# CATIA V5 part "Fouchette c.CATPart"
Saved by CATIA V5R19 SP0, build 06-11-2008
Part number: Fouchette c
Bounding box of the stored display mesh (mm): x -10 to 30, y -62.897 to 62.897, z -40 to 71.812
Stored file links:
  F:\CFAO\Hberriche\Fouchette c.CATPart
  F:\CFAO\Hberriche\Fouchette b.CATPart
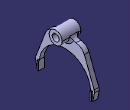
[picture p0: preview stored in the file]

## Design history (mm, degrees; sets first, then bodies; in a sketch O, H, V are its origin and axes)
Body1 (main body)
  Sketch1 on yz-plane, origin (0, 0, 0), H (0, 1, 0), V (0, 0, 1)
    line L1 (-54.7472, -20) -> (-54.7472, -40)
    point P1 (-54.7472, -20)
    point P2 (-54.7472, -40)
    point P3 (55.0096, -26.2979)
    arc A1 centre (0, -27) radius 55.1929 from (0, 28.1929) to (-54.7472, -20) ccw
    point P4 (0, -27)
    point P5 (-54.7472, -20)
    line L2 (-54.7472, -40) -> (-59.7472, -40)
    point P6 (-59.7472, -40)
    line L3 (-59.7472, -40) -> (-63.2737, -20)
    point P7 (-63.2737, -20)
    line L4 (-63.2737, -20) -> (-36.3479, 50)
    point P8 (-36.3479, 50)
    line L5 (-36.3479, 50) -> (0, 50)
    point P9 (-36.3479, 50)
    axis line L6 (0, 72.9256) -> (0, -136.9568)
    point P10 (0, 72.9256)
    point P12 (0, 50)
    point P13 (0, 28.1929)
    point P14 (0, 0)
    construction line L7 through (0, 0) direction (0, 1)
    point P17 (54.7472, -20)
    point P18 (54.7472, -40)
    point P20 (54.7472, -20)
    point P21 (59.7472, -40)
    point P22 (63.2737, -20)
    point P23 (36.3479, 50)
    point P24 (36.3479, 50)
    point P25 (0, 50)
    point P26 (0, 28.1929)
    line L8 (54.7472, -20) -> (54.7472, -40)
    arc A2 centre (0, -27) radius 55.1929 from (0, 28.1929) to (54.7472, -20) cw
    line L9 (54.7472, -40) -> (59.7472, -40)
    line L10 (59.7472, -40) -> (63.2737, -20)
    line L11 (63.2737, -20) -> (36.3479, 50)
    line L12 (36.3479, 50) -> (0, 50)
    distance P4 O = 27
    length L1 = 20
    radius A1 = 55.1929
    angle L3 L2 = 100
    length L2 = 5
    distance H L2 = 40
    distance L5 H = 50
    distance P7 H = 20
    length L4 = 75
    vertical: L1 V, L6 V
    coincidence: P4 V, P5 P1, P9 P8, P10 V, L6 P12, L6 P13, P12 P25, P13 P26, P17 P20, P23 P24
    horizontal: L2 H, L5 H
    symmetry: O P14 L6, V L7 L6, P1 P17 L6, P2 P18 L6, P5 P20 L6, P6 P21 L6, P7 P22 L6, P8 P23 L6, P9 P24 L6, P12 P25 L6, P13 P26 L6, L1 L8 L6, A1 A2 L6, L2 L9 L6, L3 L10 L6, L4 L11 L6, L5 L12 L6
  Pad1: profile Sketch1, direction (1, 0, 0), length 10
  Fillet1: radius 20, on edge [face of Pad1 from Sketch1.L4 | face of Pad1 from Sketch1.L5]; edge [face of Pad1 from Sketch1.L12 | face of Pad1 from Sketch1.L11]
  Fillet2: radius 10, on edge [face of Pad1 from Sketch1.L11 | face of Pad1 from Sketch1.L10]; edge [face of Pad1 from Sketch1.L3 | face of Pad1 from Sketch1.L4]
  Sketch2 on end face of Pad1, origin (10, 0, 0), H (0, 1, 0), V (0, 0, 1)
    circle A1 centre (0, 57.8119) radius 14
    point P1 (0, 57.8119)
    circle A2 centre (0, 57.8119) radius 7.5
    radius A2 = 7.5
    radius A1 = 14
    distance P1 H = 57.8119
    coincidence: P1 V
  Pad2: profile Sketch2, direction (1, 0, 0), length 20, mirrored extent
  Fillet3: radius 10, on edge [face of Pad2 from Sketch2.A1 | face of Pad1 from Sketch1.L12]
  Fillet4: radius 10, on edge [face of Pad1 from Sketch1.L5 | face of Pad2 from Sketch2.A1]
  Fillet5: radius 5, on edge [face of Pad2 from Sketch2.A1 | start face of Pad1]
  Fillet6: radius 5, on edge [end face of Pad1 | face of Pad2 from Sketch2.A1]
  Sketch3 on start face of Pad1, origin (0, 0, 0), H (0, -1, 0), V (0, 0, 1)
    axis line L1 (0, 18.2812) -> (0, -60.1212)
    point P1 (0, 18.2812)
    point P3 (-57.7472, -22)
    line L2 (-57.7472, -22) -> (-54.7472, -22)
    line L3 (-54.7472, -22) -> (-54.7472, -40)
    line L4 (-54.7472, -40) -> (-57.7472, -40)
    line L5 (-57.7472, -40) -> (-57.7472, -22)
    point P4 (-54.7472, -22)
    point P5 (-54.7472, -40)
    point P6 (-57.7472, -40)
    reference projected line E1 (-54.7472, -20) -> (-54.7472, -40) from edge [start face of Pad1 | face of Pad1 from Sketch1.L8]
    reference projected line E2 (-54.7472, -40) -> (-59.7472, -40) from edge [start face of Pad1 | face of Pad1 from Sketch1.L9]
    point P7 (57.7472, -22)
    point P8 (54.7472, -22)
    point P9 (54.7472, -40)
    point P10 (57.7472, -40)
    line L6 (57.7472, -22) -> (54.7472, -22)
    line L7 (54.7472, -22) -> (54.7472, -40)
    line L8 (54.7472, -40) -> (57.7472, -40)
    line L9 (57.7472, -40) -> (57.7472, -22)
    length L5 = 18
    length L2 = 3
    coincidence: P1 V, E1 L3, E2 L4
    vertical: L1 V, L3 V, L5 V
    horizontal: L2 H, L4 H
    symmetry: P3 P7 L1, P4 P8 L1, P5 P9 L1, P6 P10 L1, L2 L6 L1, L3 L7 L1, L4 L8 L1, L5 L9 L1
  Pad3: profile Sketch3, direction (-1, 0, 0), length 1.5
  Chamfer1: length 1, angle 45, on edge [start face of Pad1 | face of Pad3 from Sketch3.L5]; edge [start face of Pad1 | face of Pad3 from Sketch3.L9]
  Chamfer2: length 1, angle 45, on edge [face of Pad3 from Sketch3.L6 | start face of Pad1]; edge [face of Pad3 from Sketch3.L2 | start face of Pad1]
  Sketch4 on end face of Pad1, origin (10, 0, 0), H (0, 1, 0), V (0, 0, 1)
    point P1 (-57.7472, -22)
    line L1 (-57.7472, -22) -> (-54.7472, -22)
    line L2 (-54.7472, -22) -> (-54.7472, -40)
    line L3 (-54.7472, -40) -> (-57.7472, -40)
    line L4 (-57.7472, -40) -> (-57.7472, -22)
    point P2 (-54.7472, -22)
    point P3 (-54.7472, -40)
    point P4 (-57.7472, -40)
    reference projected line E1 (-54.7472, -40) -> (-54.7472, -20) from edge [face of Pad3 | end face of Pad1]
    reference projected line E2 (-59.7472, -40) -> (-54.7472, -40) from edge [face of Pad3 | end face of Pad1]
    axis line L5 (0, 14.1805) -> (0, -71.2709)
    point P5 (0, 14.1805)
    point P7 (57.7472, -22)
    point P8 (54.7472, -22)
    point P9 (54.7472, -40)
    point P10 (57.7472, -40)
    line L6 (57.7472, -22) -> (54.7472, -22)
    line L7 (54.7472, -22) -> (54.7472, -40)
    line L8 (54.7472, -40) -> (57.7472, -40)
    line L9 (57.7472, -40) -> (57.7472, -22)
    length L1 = 3
    length L4 = 18
    horizontal: L1 H, L3 H
    vertical: L2 V, L4 V, L5 V
    coincidence: E1 L2, E2 L3, P5 V
    symmetry: P1 P7 L5, P2 P8 L5, P3 P9 L5, P4 P10 L5, L1 L6 L5, L2 L7 L5, L3 L8 L5, L4 L9 L5
  Pad4: profile Sketch4, direction (1, 0, 0), length 1.5
  Chamfer3: length 1, angle 45, on edge [end face of Pad1 | face of Pad4 from Sketch4.L9]; edge [end face of Pad1 | face of Pad4 from Sketch4.L4]
  Chamfer4: length 1, angle 45, on edge [face of Pad4 from Sketch4.L1 | end face of Pad1]; edge [face of Pad4 from Sketch4.L6 | end face of Pad1]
